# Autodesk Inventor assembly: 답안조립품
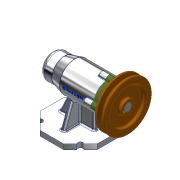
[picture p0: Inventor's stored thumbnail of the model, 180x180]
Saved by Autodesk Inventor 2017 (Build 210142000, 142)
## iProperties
Created: 2019-12
Part Number: 답안조립품
Document SubType Name: Assembly
Designer: 5-14-le
Author: 5-14-le
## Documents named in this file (12)
- C:\Users\5-14-le\Desktop\491204V1011\답안조립품.iam
- C:\Users\5-14-le\Desktop\491204V1011\본체.ipt
- C:\Users\5-14-le\Desktop\491204V1011\V벨트풀리.ipt
- C:\Users\5-14-le\Desktop\491204V1011\멈춤나사 M3.ipt
- C:\Users\5-14-le\Desktop\491204V1011\베어링 6004.ipt
- C:\Users\5-14-le\Desktop\491204V1011\베어링 51202.ipt
- C:\Users\5-14-le\Desktop\491204V1011\볼트 M4.ipt
- C:\Users\5-14-le\Desktop\491204V1011\어댑터슬리브.ipt
- C:\Users\5-14-le\Desktop\491204V1011\오일 실.ipt
- C:\Users\5-14-le\Desktop\491204V1011\축.ipt
- C:\Users\5-14-le\Desktop\491204V1011\커버.ipt
- C:\Users\5-14-le\Desktop\491204V1011\키 5 x 5 x 16.ipt
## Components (1 placed, 1 different names)
1. V벨트풀리:1
